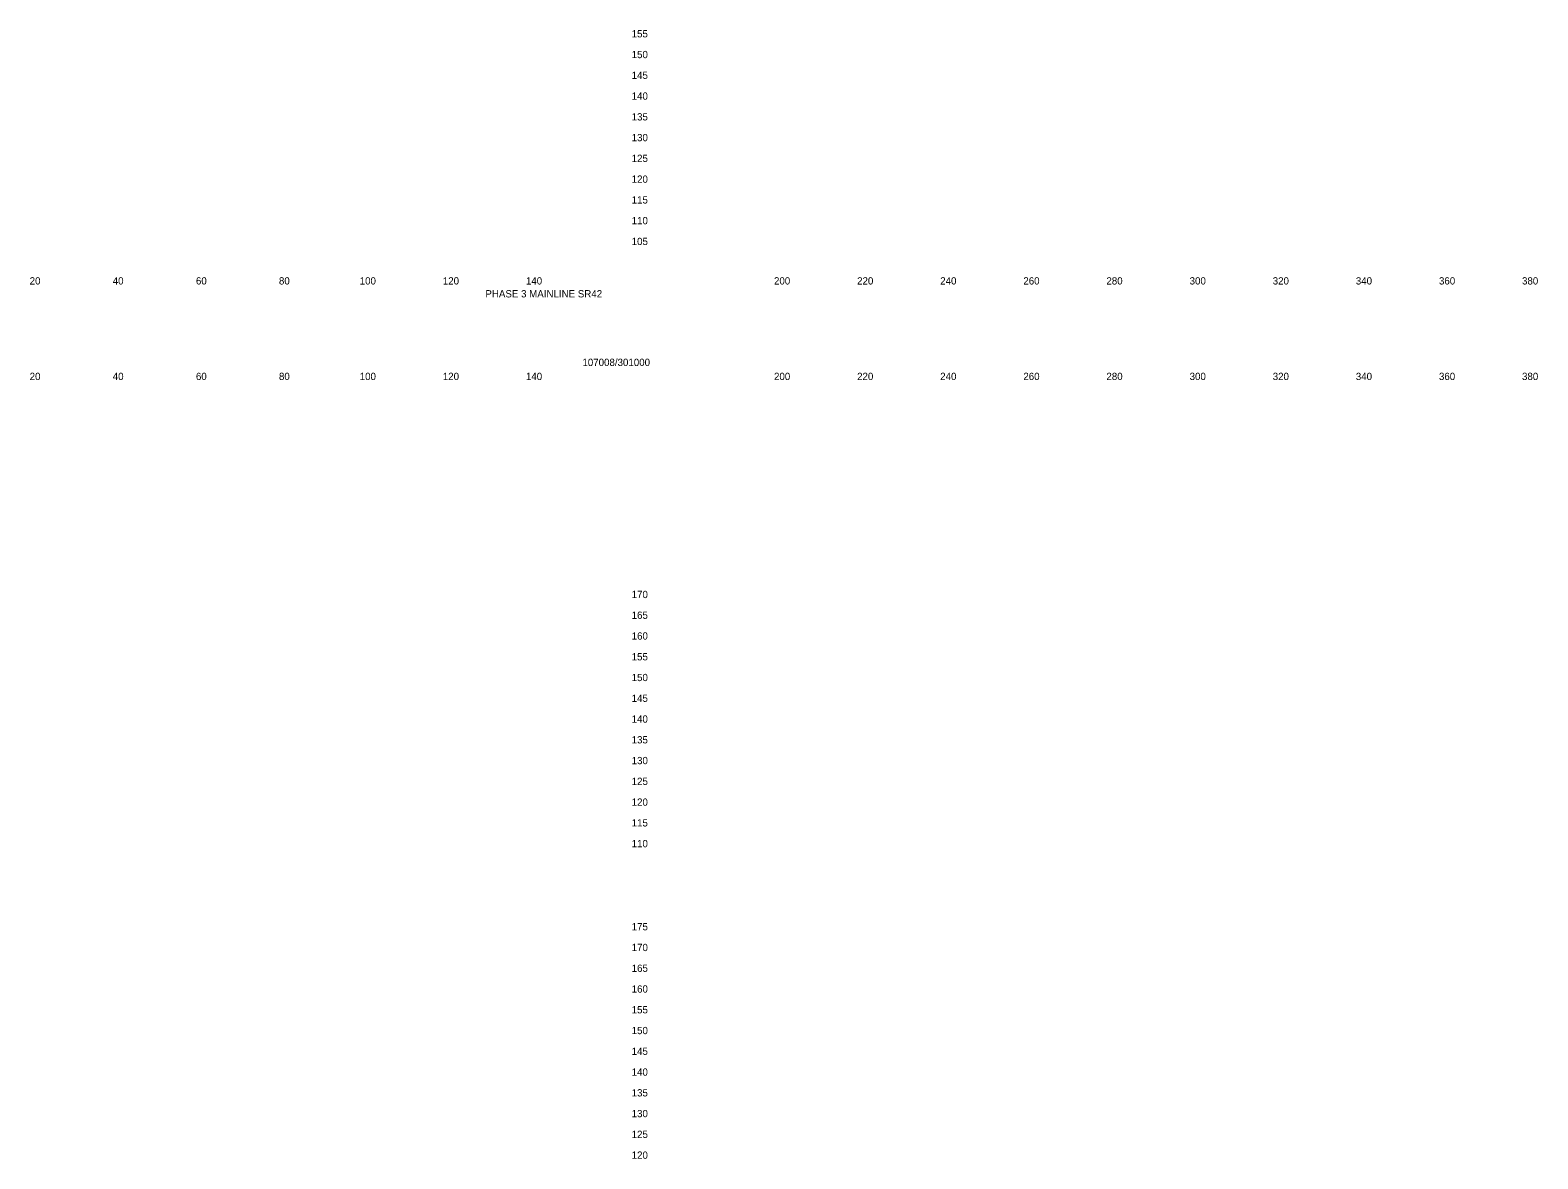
# Model space of a CAD drawing. Extents: x 21281 to 22024, y 6472 to 15198.
# Drawn here: x 21661.4 to 22024.2, y 12474.8 to 12746.6 of the extents above; entities that cross this region are included whole.
import ezdxf

# ---------------------------------------------------------------- set-up
doc = ezdxf.new("R2010")
doc.units = 0
doc.layers.add('Draft_XS_Grid', color=7, linetype='Continuous')
doc.layers.add('Draft_XS_Text', color=7, linetype='Continuous')

msp = doc.modelspace()

# ---------------------------------------------------------------- texts
at = {"layer": 'Draft_XS_Grid'}
for s, p in [('  155  ', (21804.84, 12744.84)), ('  150  ', (21804.84, 12739.84)), ('  145  ', (21804.84, 12734.84)), ('  140  ', (21804.84, 12729.84)), ('  135  ', (21804.84, 12724.84)), ('  130  ', (21804.84, 12719.84)), ('  125  ', (21804.84, 12714.84)), ('  120  ', (21804.84, 12709.84)), ('  115  ', (21804.84, 12704.84)), ('  110  ', (21804.84, 12699.84)), ('  105  ', (21804.84, 12694.84)), ('  170  ', (21804.84, 12609.84)), ('  165  ', (21804.84, 12604.84)), ('  160  ', (21804.84, 12599.84)), ('  155  ', (21804.84, 12594.84)), ('  150  ', (21804.84, 12589.84)), ('  145  ', (21804.84, 12584.84)), ('  140  ', (21804.84, 12579.84)), ('  135  ', (21804.84, 12574.84)), ('  130  ', (21804.84, 12569.84)), ('  125  ', (21804.84, 12564.84)), ('  120  ', (21804.84, 12559.84)), ('  115  ', (21804.84, 12554.84)), ('  110  ', (21804.84, 12549.84)), ('  175  ', (21804.84, 12529.84)), ('  170  ', (21804.84, 12524.84)), ('  165  ', (21804.84, 12519.84)), ('  160  ', (21804.84, 12514.84)), ('  155  ', (21804.84, 12509.84)), ('  150  ', (21804.84, 12504.84)), ('  145  ', (21804.84, 12499.84)), ('  140  ', (21804.84, 12494.84)), ('  135  ', (21804.84, 12489.84)), ('  130  ', (21804.84, 12484.84)), ('  125  ', (21804.84, 12479.84)), ('  120  ', (21804.84, 12474.84))]:
    msp.add_text(s, height=1.75, dxfattribs=at).set_placement(p)
at = {"layer": 'Draft_XS_Text'}
for s, p in [('  20  ', (21659.95, 12685.34)), ('  40  ', (21679.95, 12685.34)), ('  60  ', (21699.97, 12685.34)), ('  80  ', (21719.95, 12685.34)), ('  100  ', (21739.39, 12685.34)), ('  120  ', (21759.39, 12685.34)), ('  140  ', (21779.39, 12685.34)), ('  200  ', (21839.1, 12685.34)), ('  220  ', (21859.1, 12685.34)), ('  240  ', (21879.1, 12685.34)), ('  260  ', (21899.11, 12685.34)), ('  280  ', (21919.1, 12685.34)), ('  300  ', (21939.13, 12685.34)), ('  320  ', (21959.13, 12685.34)), ('  340  ', (21979.13, 12685.34)), ('  360  ', (21999.14, 12685.34)), ('  380  ', (22019.13, 12685.34)), ('PHASE 3 MAINLINE SR42', (21770.94, 12682.23)), ('107008/301000', (21794.29, 12665.72)), ('  20  ', (21659.95, 12662.34)), ('  40  ', (21679.95, 12662.34)), ('  60  ', (21699.97, 12662.34)), ('  80  ', (21719.95, 12662.34)), ('  100  ', (21739.39, 12662.34)), ('  120  ', (21759.39, 12662.34)), ('  140  ', (21779.39, 12662.34)), ('  200  ', (21839.1, 12662.34)), ('  220  ', (21859.1, 12662.34)), ('  240  ', (21879.1, 12662.34)), ('  260  ', (21899.11, 12662.34)), ('  280  ', (21919.1, 12662.34)), ('  300  ', (21939.13, 12662.34)), ('  320  ', (21959.13, 12662.34)), ('  340  ', (21979.13, 12662.34)), ('  360  ', (21999.14, 12662.34)), ('  380  ', (22019.13, 12662.34))]:
    msp.add_text(s, height=1.75, dxfattribs=at).set_placement(p)

doc.saveas('drawing.dxf')
